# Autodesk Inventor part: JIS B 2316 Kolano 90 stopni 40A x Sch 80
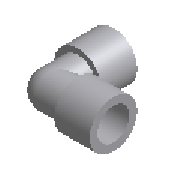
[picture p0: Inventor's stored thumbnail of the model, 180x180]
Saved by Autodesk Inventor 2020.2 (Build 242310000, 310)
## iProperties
Manager: www.cadconsulting.pl
Company: Fabian Stasiak CAD Consulting
NAME: PIPING: JIS B 2316 90 Deg Elbow
DATA: <meta><inlinegroups number="0" deflen="0"></inlinegroups><connections number="2"></connections><angles><a>1.5707963267949</a></angles></meta>
IsCustomPart: 0
Created: 2014-02
Part Number: JIS B 2316 Kolano 90 stopni 40A x Sch 80
Material: Stal
Description: Kolano
Document SubType Name: Modeling
Standard: JIS B 2316
Designer: F.Stasiak
Standards Organization: JIS
Language: pl-PL
Size Designation: 40A x Sch 80
Categories: <MemberInstance><Categories><Category DisplayName="Rury cienko- i grubościenne" InternalName="4347fa0f-2144-441d-94cd-e3e15c92b736" Mnemonic="TUBEANDPIPE"><Cate
Density: 1 g/cm^3
Appearance: Płyta
Catalog Web Link: www.expertbooks.pl
Author: F.Stasiak
Subject: Zbiór ćwiczeń. Autodesk Inventor 2020. Kurs Professional
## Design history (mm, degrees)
sketch "Sketch1"
  geometry: L1 (0, 0)-(0, 44.5); L2 (0, 44.5)-(-44.5, 44.5); L3 (0, 0)-(-44.5, 0); L4 (-44.5, 0)-(-44.5, 44.5); L5 (0, 44.5)-(-44.5, 0)
  constraints: 10 end point, 2 parallel, 1 coincident, 1 perpendicular, 1 vertical
  dimensions: "d8" = 44.5 distance of L1.start L1.end (= G + C1); "d9" = 44.5 distance of L1.end L2.end (= G + C1)
workplane "Work Plane1"
sketch "Sketch2"
  geometry: C1 r 20.6 at (0, 0); C2 r 26.2 at (0, 0)
  constraints: 2 centre point, 1 coincident, 1 concentric
  dimensions: "d0" = 41.2 diameter of C1 (= D); "d1" = 52.4 diameter of C2 (= D + 2 x T)
extrude "Extrusion1" new body sketch "Sketch2" taper "d2" = 0 deg; stored distance "d49" = 70.7 (= C1 + G + T + 0.5 x D)
workplane "Work Plane2"
sketch "Sketch3"
  geometry: L1 (0, 44.5)-(0, 0); L2 (-26.2, 0)-(26.2, 0) reference; C1 r 26.2 at (0, 44.5); C2 r 20.6 at (0, 44.5)
  constraints: 2 centre point, 2 end point, 1 coincident, 1 concentric, 1 midpoint, 1 vertical
  dimensions: "d4" = 44.5 distance of L1.start L1.end (= G + C1); "d5" = 41.2 diameter of C2 (= D); "d6" = 52.4 diameter of C1 (= D + 2 x T)
extrude "Extrusion2" join sketch "Sketch3" taper "d7" = 0 deg; stored distance "d55" = 70.7 (= C1 + G + 0.5 x D + T)
sketch "Sketch4"
  geometry: C1 r 26.2 at (0, 0) reference; C2 r 30.15 at (0, 0)
  constraints: 1 centre point, 1 coincident, 1 concentric
  dimensions: "d11" = 60.3 diameter of C2 (= S + 2 x T)
extrude "Extrusion3" join sketch "Sketch4" distance "d12" = 18.3 (= C1 + T); taper "d13" = 0 deg
sketch "Sketch5"
  geometry: C1 r 26.2 at (0, 0) reference; C2 r 30.15 at (0, 0)
  constraints: 1 centre point, 1 coincident, 1 concentric
  dimensions: "d14" = 60.3 diameter of C2 (= S + 2 x T)
extrude "Extrusion4" join sketch "Sketch5" distance "d15" = 18.3 (= C1 + T); taper "d16" = 0 deg
sketch "Sketch6"
  geometry: C1 r 20.6 at (0, 0) reference; C2 r 24.55 at (0, 0)
  constraints: 1 centre point, 1 coincident, 1 concentric
  dimensions: "d17" = 49.1 diameter of C2 (= S)
extrude "Extrusion5" cut sketch "Sketch6" distance "d18" = 12.7 (= C1); taper "d19" = 0 deg
sketch "Sketch7"
  geometry: C1 r 20.6 at (0, 0) reference; C2 r 24.55 at (0, 0)
  constraints: 1 centre point, 1 coincident, 1 concentric
  dimensions: "d20" = 49.1 diameter of C2 (= S)
extrude "Extrusion6" cut sketch "Sketch7" distance "d21" = 12.7 (= C1); taper "d22" = 0 deg
fillet "Fillet1" dims "d23" = 15 (= G - 3 x T), "d24" = 20.6 (= G - 2 x T)
workaxis "Work Axis1"
workpoint "Work Point1"
workpoint "Work Point2"
workaxis "Work Axis2"
workpoint "Work Point3"
workpoint "Work Point4"
body "Solid1"
other parameters: "S" = 49.1 [user parameter; used in 4 equation terms], "D" = 41.2 [user parameter; used in 6 equation terms], "T" = 5.6 [user parameter; used in 10 equation terms], "C1" = 12.7 [user parameter; used in 10 equation terms], "G" = 31.8 [user parameter; used in 8 equation terms], "d3" = 44.5 (= G + C1), "d10" = 90 deg, "Size_Designation" = 12.345 [user parameter]
